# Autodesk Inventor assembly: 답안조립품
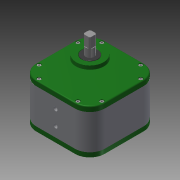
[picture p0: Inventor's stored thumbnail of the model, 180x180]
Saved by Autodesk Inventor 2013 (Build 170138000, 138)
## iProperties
Created: 2017-11
Part Number: 답안조립품
Document SubType Name: Assembly
Designer: Administrator
Mass: 3103.25 g
Surface Area: 2353.72 cm^2
Volume: 855.505 cm^3
Density: 3.62739 g/cm^3
Author: Administrator
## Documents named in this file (11)
- C:\Users\Administrator\Desktop\371108V1002\답안조립품.iam
- C:\Users\Administrator\Desktop\371108V1002\본체.ipt
- C:\Users\Administrator\Desktop\371108V1002\뒤커버.ipt
- C:\Users\Administrator\Desktop\371108V1002\메인축.ipt
- C:\Users\Administrator\Desktop\371108V1002\베어링 608.ipt
- C:\Users\Administrator\Desktop\371108V1002\베어링 6003.ipt
- C:\Users\Administrator\Desktop\371108V1002\볼트 M4.ipt
- C:\Users\Administrator\Desktop\371108V1002\서브축.ipt
- C:\Users\Administrator\Desktop\371108V1002\앞커버.ipt
- C:\Users\Administrator\Desktop\371108V1002\오일실 8 22 7.ipt
- C:\Users\Administrator\Desktop\371108V1002\오일실 17 32 8.ipt
